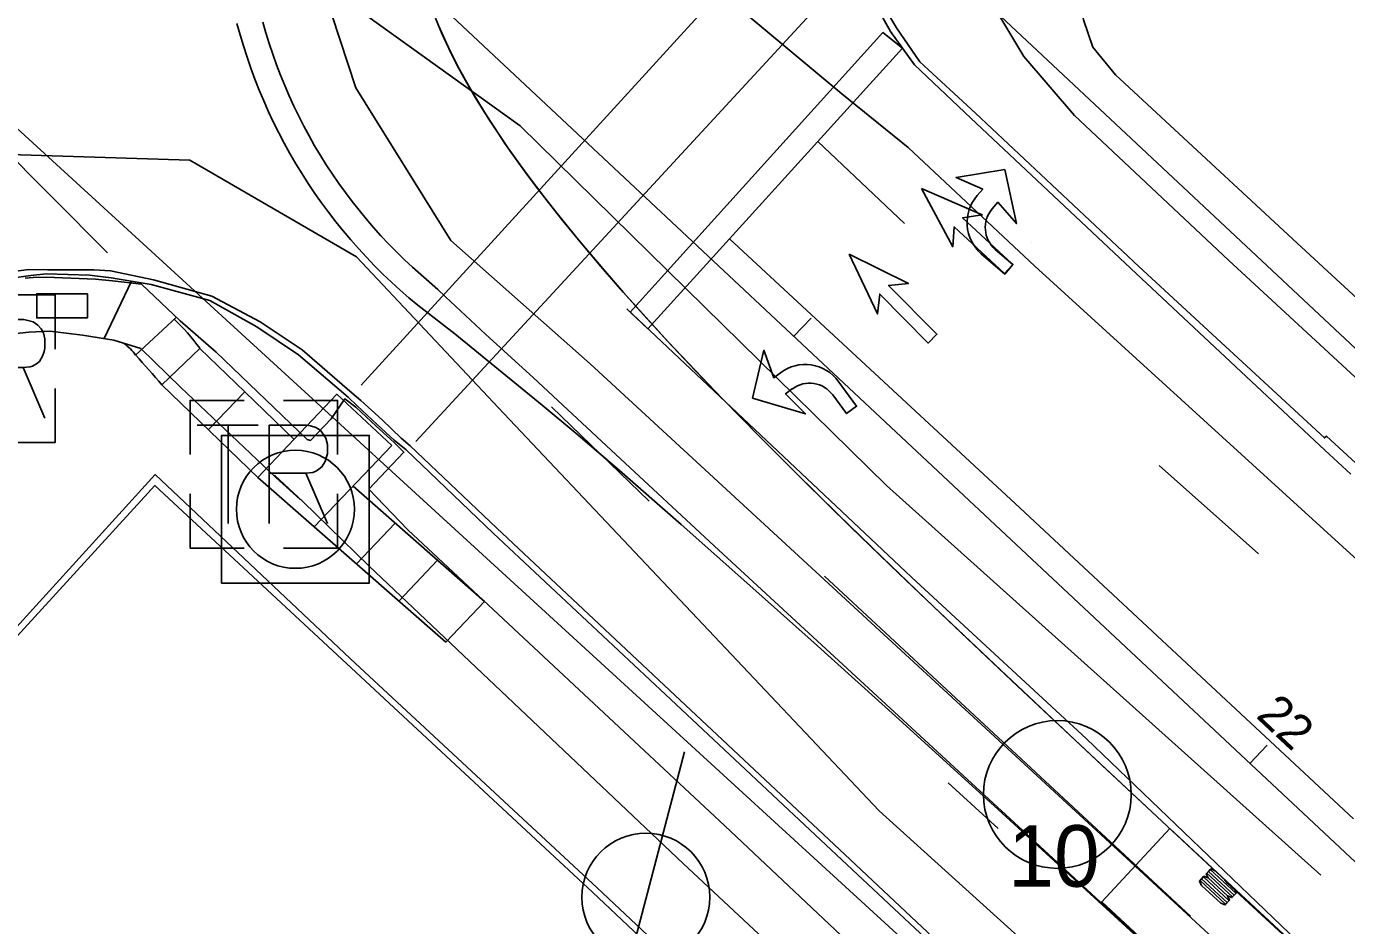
# Model space of a CAD drawing. Extents: x 1475900 to 1484331, y 375914 to 383395.
# Drawn here: x 1479629.9 to 1479735.5, y 379825.7 to 379897.7 of the extents above; entities that cross this region are included whole.
import ezdxf

# ---------------------------------------------------------------- set-up
doc = ezdxf.new("R2010")
doc.units = 0
for name, color, linetype in [('Default', 7, 'Continuous'), ('LT_X_Poles', 7, 'Continuous'), ('PM_X_Cells', 7, 'Continuous'), ('PM_X_Cells (Construction)', 7, 'Continuous'), ('PM_X_Channelizing_Line', 7, 'Continuous'), ('PM_X_CL_Double_Solid', 7, 'Continuous'), ('PM_X_Crosswalk', 7, 'Continuous'), ('PM_X_Lane_Line', 7, 'Continuous'), ('PM_X_Misc', 7, 'Continuous'), ('PM_X_Stop_Line', 7, 'Continuous'), ('PV_X_Curb', 7, 'Continuous'), ('PV_X_Walk', 7, 'Continuous'), ('RW_X_CL_20', 7, 'Continuous'), ('RW_X_Esmt_SH', 7, 'Continuous'), ('RW_X_Text', 7, 'Continuous'), ('SG_X_Poles', 7, 'Continuous'), ('SG_X_PullBox', 7, 'Continuous'), ('SG_X_PullBox (Construction)', 7, 'Continuous')]:
    doc.layers.add(name, color=color, linetype=linetype)

# ---------------------------------------------------------------- blocks, each defined once
blk = doc.blocks.new('SPOLE')
at = {"layer": 'SG_X_Poles'}
blk.add_lwpolyline([(-0.01905, -0.01905), (0.01905, -0.01905), (0.01905, 0.01905), (-0.01905, 0.01905)], close=True, dxfattribs=at)
blk.add_circle((0, 0), 0.01524, dxfattribs=at)
blk = doc.blocks.new('POINT_DISPLAY')
at = {"layer": 'Default'}
blk.add_line((0, 0), (0, 0), dxfattribs=at)
blk = doc.blocks.new('SIGPB')
at = {"layer": 'SG_X_PullBox'}
for p, q in [((-0.01722, 0.0127), (-0.00142, 0.0127)), ((-0.00922, 0.0127), (-0.00922, -0.0127)), ((0.01082, 0.0003), (0.01642, -0.0127))]:
    blk.add_line(p, q, dxfattribs=at)
for points in [[(-0.00508, 0.01905), (-0.01905, 0.01905), (-0.01905, 0.00508)], [(0.01905, 0.00508), (0.01905, 0.01905), (0.00508, 0.01905)], [(0.00142, -0.0127), (0.00142, 0.0127), (0.01102, 0.0127), (0.01202, 0.0125), (0.01342, 0.0121), (0.01402, 0.0117), (0.01462, 0.0113), (0.01542, 0.0103), (0.01602, 0.0093), (0.01642, 0.0077), (0.01642, 0.0053), (0.01622, 0.0045), (0.01582, 0.0033), (0.01502, 0.0019), (0.01422, 0.0013), (0.01362, 0.0009), (0.01322, 0.0007), (0.01262, 0.0005), (0.01082, 0.0003), (0.00142, 0.0003)], [(-0.01905, -0.00508), (-0.01905, -0.01905), (-0.00508, -0.01905)], [(0.00508, -0.01905), (0.01905, -0.01905), (0.01905, -0.00508)]]:
    blk.add_lwpolyline(points, dxfattribs=at)
at = {"layer": 'SG_X_PullBox (Construction)'}
blk.add_blockref('POINT_DISPLAY', (0, 0), dxfattribs=at)
blk = doc.blocks.new('LPOLE')
at = {"layer": 'LT_X_Poles'}
blk.add_lwpolyline([(0.00999, 0.03751), (-0.01001, -0.0385), (0.02, -0.0385)], dxfattribs=at)
blk.add_circle((0, 0), 0.01651, dxfattribs=at)
blk = doc.blocks.new('PMTHR')
at = {"layer": 'PM_X_Cells'}
blk.add_lwpolyline([(0, 0), (-1.27, -0.441), (-1.016, -0.127), (-2.413, -0.127), (-2.413, 0.127), (-1.016, 0.127), (-1.27, 0.441)], close=True, dxfattribs=at)
at = {"layer": 'PM_X_Cells (Construction)'}
for p in [(0, 0), (-2.413, 0)]:
    blk.add_blockref('POINT_DISPLAY', p, dxfattribs=at)
blk = doc.blocks.new('PMLFT')
at = {"layer": 'PM_X_Cells'}
for points in [[(-0.569, 0), (-0.569, 0), (-0.569, 0.169), (0, 0), (-0.65, 0.762), (-1.544, 0.085), (-0.975, 0.169), (-0.975, -0.009)], [(-1.559, -0.593), (-2.032, -0.593), (-2.032, -0.847), (-1.402, -0.847)]]:
    blk.add_lwpolyline(points, dxfattribs=at)
for centre, radius, end in [((-1.559, -0.009), 0.583, 0), ((-1.402, -0.013), 0.833, 0.9085)]:
    blk.add_arc(centre, radius, 270, end, dxfattribs=at)
at = {"layer": 'PM_X_Cells (Construction)'}
for p in [(-2.032, 0), (0, 0)]:
    blk.add_blockref('POINT_DISPLAY', p, dxfattribs=at)
blk = doc.blocks.new('PMRT')
at = {"layer": 'PM_X_Cells'}
for points in [[(-1.559, 0.593), (-2.032, 0.593), (-2.032, 0.847), (-1.402, 0.847)], [(-0.569, 0), (-0.569, 0), (-0.569, -0.169), (0, 0), (-0.65, -0.762), (-1.544, -0.085), (-0.975, -0.169), (-0.975, 0.009)]]:
    blk.add_lwpolyline(points, dxfattribs=at)
for centre, radius, start in [((-1.402, 0.013), 0.833, 359.0915), ((-1.559, 0.009), 0.583, 0)]:
    blk.add_arc(centre, radius, start, 90, dxfattribs=at)
at = {"layer": 'PM_X_Cells (Construction)'}
for p in [(-2.032, 0), (0, 0)]:
    blk.add_blockref('POINT_DISPLAY', p, dxfattribs=at)

msp = doc.modelspace()

# ---------------------------------------------------------------- linework, layer by layer
at = {"layer": 'PM_X_Channelizing_Line'}
msp.add_lwpolyline([(1479686.16, 379880.68), (1479709.4, 379859.14), (1479736.1, 379834.26)], dxfattribs=at)
at = {"layer": 'PM_X_CL_Double_Solid'}
msp.add_lwpolyline([(1479794.22, 379768.77), (1479779.09, 379781.77), (1479763.16, 379795.43), (1479746.62, 379810.62), (1479732.24, 379823.87), (1479714.72, 379840.65), (1479700.71, 379853.61), (1479677.93, 379875.07)], dxfattribs=at)
at = {"layer": 'PM_X_Crosswalk'}
for p, q in [((1479636.37, 379879.55), (1479574.01, 379942.24)), ((1479656.67, 379868.95), (1479694.22, 379910.08)), ((1479661.06, 379864.45), (1479696.23, 379902.55))]:
    msp.add_line(p, q, dxfattribs=at)
at = {"layer": 'PM_X_Lane_Line'}
for p, q in [((1479700.15, 379881.9), (1479693.22, 379888.46)), ((1479679.73, 379859.67), (1479671.91, 379867.24)), ((1479728.5, 379855.47), (1479720.54, 379862.54)), ((1479707.65, 379833.48), (1479703.66, 379837.14))]:
    msp.add_line(p, q, dxfattribs=at)
at = {"layer": 'PM_X_Misc'}
msp.add_line((1479693.75, 379853.68), (1479723.06, 379826.47), dxfattribs=at)
for points in [[(1479719.19, 379824.44), (1479707.65, 379835), (1479699.7, 379842.23), (1479692.92, 379848.35), (1479687.31, 379853.36), (1479682.27, 379857.82), (1479677.13, 379862.31), (1479673.86, 379865.13), (1479671.15, 379867.37), (1479664.18, 379873.07), (1479661.21, 379875.35), (1479660.49, 379875.95), (1479659.78, 379876.57), (1479659.09, 379877.21), (1479658.41, 379877.85), (1479657.74, 379878.52), (1479657.09, 379879.2), (1479656.46, 379879.89), (1479655.84, 379880.59), (1479655.23, 379881.31), (1479654.64, 379882.04), (1479654.07, 379882.79), (1479653.51, 379883.54), (1479652.97, 379884.31), (1479652.44, 379885.09), (1479651.94, 379885.88), (1479651.45, 379886.68), (1479650.97, 379887.5), (1479650.52, 379888.32), (1479650.08, 379889.15), (1479649.66, 379889.99), (1479649.26, 379890.84), (1479648.88, 379891.7), (1479648.51, 379892.57), (1479648.17, 379893.44), (1479647.84, 379894.32), (1479647.54, 379895.21), (1479647.25, 379896.1), (1479646.98, 379897), (1479646.73, 379897.91)], [(1479735, 379809.93), (1479685.31, 379855.76), (1479676.69, 379863.75), (1479670.46, 379869.55), (1479666.63, 379873.05), (1479663.42, 379876.03), (1479662.8, 379876.62), (1479660.79, 379878.39), (1479660.13, 379879), (1479659.49, 379879.63), (1479658.87, 379880.26), (1479658.25, 379880.92), (1479657.65, 379881.58), (1479657.07, 379882.26), (1479656.5, 379882.95), (1479655.95, 379883.66), (1479655.41, 379884.37), (1479654.88, 379885.1), (1479654.38, 379885.84), (1479653.88, 379886.59), (1479653.41, 379887.35), (1479652.95, 379888.12), (1479652.51, 379888.9), (1479652.08, 379889.68), (1479651.67, 379890.48), (1479651.28, 379891.29), (1479650.91, 379892.1), (1479650.55, 379892.93), (1479650.22, 379893.76), (1479649.9, 379894.59), (1479649.6, 379895.44), (1479649.31, 379896.29), (1479649.05, 379897.14), (1479648.8, 379898)], [(1479662.61, 379898.32), (1479663.13, 379897.09), (1479663.71, 379895.84), (1479664.34, 379894.59), (1479665.02, 379893.34), (1479665.75, 379892.08), (1479666.52, 379890.83), (1479667.33, 379889.57), (1479668.17, 379888.31), (1479669.05, 379887.06), (1479669.96, 379885.81), (1479671.37, 379883.95), (1479672.82, 379882.1), (1479674.32, 379880.27), (1479675.86, 379878.45), (1479677.43, 379876.64), (1479679.03, 379874.85), (1479681.2, 379872.48), (1479683.41, 379870.14), (1479685.66, 379867.8), (1479688.49, 379864.91), (1479691.37, 379862.03), (1479694.85, 379858.61), (1479698.36, 379855.2), (1479702.49, 379851.24), (1479707.83, 379846.17), (1479713.8, 379840.57), (1479721.58, 379833.3), (1479725.78, 379829.4), (1479725.98, 379829.12), (1479740.44, 379815.79)], [(1479662.85, 379897.74), (1479663.49, 379896.33), (1479663.82, 379895.64), (1479664.51, 379894.28), (1479665.25, 379892.95), (1479665.63, 379892.29), (1479666.84, 379890.32), (1479667.69, 379889.04), (1479668.55, 379887.77), (1479669.91, 379885.88), (1479670.82, 379884.66), (1479672.24, 379882.83), (1479674.17, 379880.45), (1479676.17, 379878.1), (1479677.67, 379876.38), (1479679.72, 379874.1), (1479681.28, 379872.4), (1479682.87, 379870.71), (1479685.53, 379867.93), (1479688.76, 379864.64), (1479692.01, 379861.39), (1479695.87, 379857.61), (1479699.71, 379853.9), (1479704.18, 379849.63), (1479709.2, 379844.88), (1479715.95, 379838.55), (1479724.38, 379830.7), (1479743.38, 379813.07)], [(1479726.67, 379828.3), (1479724.62, 379830.2), (1479724.49, 379830.06), (1479726.54, 379828.15), (1479726.4, 379828.01), (1479724.35, 379829.91), (1479724.3, 379829.86), (1479724.47, 379829.53), (1479726.01, 379828.1), (1479726.36, 379827.96), (1479726.72, 379828.35), (1479726.55, 379828.68), (1479725.01, 379830.11), (1479724.67, 379830.25), (1479724.3, 379829.86)], [(1479726.13, 379827.71), (1479724.08, 379829.62), (1479723.94, 379829.47), (1479725.99, 379827.57), (1479725.86, 379827.42), (1479723.81, 379829.33), (1479723.76, 379829.28), (1479723.93, 379828.94), (1479725.47, 379827.51), (1479725.81, 379827.37), (1479726.18, 379827.76), (1479726.01, 379828.1), (1479724.47, 379829.53), (1479724.12, 379829.67), (1479723.76, 379829.28)]]:
    msp.add_lwpolyline(points, dxfattribs=at)
msp.add_lwpolyline([(1479737.93, 379807.21), (1479715.94, 379827.62), (1479718.67, 379830.55), (1479721.39, 379833.48), (1479743.38, 379813.07), (1479740.65, 379810.14)], close=True, dxfattribs=at)
msp.add_circle((1479712.39, 379836.21), 5.91, dxfattribs=at)
at = {"layer": 'PM_X_Stop_Line'}
msp.add_lwpolyline([(1479700, 379895.92), (1479698.43, 379897.17), (1479678.21, 379874.81), (1479679.62, 379873.47)], close=True, dxfattribs=at)
at = {"layer": 'PV_X_Curb'}
msp.add_line((1479636.09, 379872.69), (1479638.29, 379877.28), dxfattribs=at)
for points in [[(1479735.87, 379861.85), (1479733.79, 379863.76), (1479718.7, 379877.9), (1479705.48, 379890.33), (1479700.95, 379894.58), (1479699.05, 379897.26), (1479697.78, 379899.5), (1479696.44, 379902.73), (1479695.78, 379905.4), (1479695.47, 379907.42), (1479695.14, 379911.53), (1479695.08, 379915.32), (1479695.47, 379917.32), (1479696.05, 379920.61), (1479697.32, 379923.3), (1479700.06, 379927.56), (1479702.83, 379930.77), (1479705.86, 379933.57), (1479707.03, 379934.35), (1479708.06, 379934.88), (1479711.18, 379937.55)], [(1479714.57, 379931.72), (1479714.77, 379922.6), (1479714.23, 379900.01), (1479714.49, 379898.19), (1479715.22, 379896), (1479717.04, 379893.8), (1479731.94, 379880.01), (1479745.71, 379867.31), (1479763.19, 379850.75), (1479775.06, 379839.58), (1479781.93, 379833.12), (1479783.78, 379830.71), (1479784.21, 379828.71), (1479783.14, 379825.91)], [(1479738.29, 379860.89), (1479733.93, 379864.88), (1479733.77, 379864.74), (1479718.9, 379878.45), (1479705.83, 379890.72), (1479701.38, 379894.84), (1479699.53, 379897.55), (1479698.18, 379899.76)], [(1479624.52, 379877.49), (1479630.08, 379878.22), (1479631.57, 379878.19), (1479635.27, 379878.18), (1479636.61, 379878.11), (1479640.05, 379877.39), (1479644.71, 379876.09), (1479648.6, 379874.02), (1479651.95, 379871.78), (1479655.96, 379868.33), (1479656.65, 379867.73), (1479658.34, 379866.2), (1479659.87, 379864.73), (1479660.6, 379864.1), (1479667.53, 379857.52), (1479681.36, 379844.56), (1479695.38, 379831.42), (1479709.51, 379818.13)], [(1479624.77, 379877), (1479630.24, 379877.74), (1479631.47, 379877.86), (1479634.93, 379877.76), (1479636.66, 379877.55), (1479639.86, 379877.01), (1479644.56, 379875.73), (1479648.33, 379873.64), (1479651.66, 379871.4), (1479655.64, 379868), (1479656.34, 379867.3), (1479657.96, 379865.82), (1479659.31, 379864.57), (1479660.28, 379863.79), (1479667.24, 379857.12), (1479681.02, 379844.21), (1479695.13, 379830.98), (1479709.33, 379817.71)], [(1479752.34, 379756.82), (1479734.89, 379773.49), (1479717.23, 379789.66), (1479699.3, 379806.4), (1479688.16, 379794.93), (1479685.53, 379793.9), (1479682.73, 379795.16), (1479681.26, 379797.55), (1479682.49, 379800.75), (1479693.46, 379811.91), (1479675.55, 379828.75), (1479655.83, 379847.06), (1479640.19, 379861.81), (1479628.56, 379849)], [(1479751.93, 379756.63), (1479734.45, 379772.98), (1479716.7, 379789.46), (1479699.4, 379805.74), (1479688.56, 379794.79), (1479685.72, 379793.29), (1479682.29, 379794.8), (1479680.73, 379797.25), (1479682.17, 379801.19), (1479692.65, 379811.91), (1479675.18, 379828.39), (1479655.51, 379846.68), (1479640.15, 379860.93), (1479629.13, 379848.87)]]:
    msp.add_lwpolyline(points, dxfattribs=at)
for points in [[(1479634.76, 379876.27), (1479634.76, 379874.34), (1479630.71, 379874.34), (1479630.71, 379876.27)], [(1479659.12, 379864.14), (1479652.91, 379857.63), (1479648.4, 379861.58), (1479654.73, 379868.23)]]:
    msp.add_lwpolyline(points, close=True, dxfattribs=at)
at = {"layer": 'PV_X_Walk'}
for p, q in [((1479641.88, 379874.41), (1479638.62, 379871.36)), ((1479643.77, 379871.9), (1479640.72, 379868.99)), ((1479643.77, 379871.9), (1479647.37, 379868.43)), ((1479640.72, 379868.99), (1479648.4, 379861.58)), ((1479647.37, 379868.43), (1479644.44, 379865.4)), ((1479647.37, 379868.43), (1479651.32, 379864.61)), ((1479656.02, 379860.89), (1479666.55, 379851.65)), ((1479652.91, 379857.63), (1479663.45, 379848.39)), ((1479659.4, 379857.92), (1479656.3, 379854.66)), ((1479662.79, 379854.95), (1479659.68, 379851.69)), ((1479666.55, 379851.65), (1479663.45, 379848.39))]:
    msp.add_line(p, q, dxfattribs=at)
for points in [[(1479714.41, 379931.65), (1479709.59, 379929.39), (1479706.36, 379927.01), (1479703.83, 379924.36), (1479702.38, 379922.18), (1479701.6, 379920.68), (1479701.23, 379918.28), (1479701.22, 379916.7), (1479701.87, 379912.68), (1479703.86, 379906.89), (1479705.42, 379903.15), (1479707.31, 379899.27), (1479709.71, 379895.26), (1479713.76, 379890.53), (1479726.08, 379878.96), (1479737.97, 379867.99), (1479746.24, 379860.49), (1479749.39, 379863.57), (1479751.94, 379861.3), (1479749.04, 379858.04), (1479762.48, 379845.22), (1479775.26, 379833.23), (1479781.25, 379827.72), (1479783.04, 379825.88)], [(1479705.73, 379814.89), (1479685.77, 379833.71), (1479660.41, 379857.39), (1479657.29, 379860.63), (1479660.09, 379863.59), (1479659.32, 379864.38), (1479657.86, 379865.69), (1479656.25, 379867.19), (1479655.37, 379867.88), (1479654.27, 379866.26), (1479652.63, 379864.54), (1479652.35, 379864.61), (1479645.06, 379871.59), (1479642.19, 379874.12), (1479639.08, 379877.04), (1479636.77, 379877.32), (1479635.41, 379877.45), (1479631.46, 379877.61), (1479630.42, 379877.57), (1479629.78, 379877.53)], [(1479767.05, 379754.29), (1479759.06, 379761.03), (1479757.31, 379762.48), (1479754.26, 379765.1), (1479744.26, 379773.56), (1479732.86, 379783.69), (1479719.35, 379796.38), (1479703.03, 379811.46), (1479682.44, 379830.69), (1479657.3, 379854.47), (1479652, 379859.64), (1479649.77, 379861.74), (1479651.8, 379859.82), (1479649.83, 379861.57), (1479642.24, 379868.78), (1479639.04, 379871.89), (1479636.88, 379872.56), (1479634.38, 379872.97), (1479631.75, 379873.28), (1479630.08, 379873.21), (1479625.85, 379872.76)]]:
    msp.add_lwpolyline(points, dxfattribs=at)
for centre, radius, start, end in [((1479628.39, 379860.4), 19.21, 36.808, 46.2666), ((1479635.39, 379869.13), 3.92, 34.5576, 53.9557), ((1479511.61, 379756.72), 171.1, 41.007, 42.0676)]:
    msp.add_arc(centre, radius, start, end, dxfattribs=at)
at = {"layer": 'RW_X_CL_20'}
for p, q in [((1479691.31, 379872.87), (1479692.68, 379874.33)), ((1479727.81, 379838.69), (1479729.18, 379840.15))]:
    msp.add_line(p, q, dxfattribs=at)
msp.add_lwpolyline([(1477185.15, 382318.79), (1478151.68, 381373.49), (1479566.7, 379989.54), (1480555.97, 379063.33), (1481343.87, 378335.5), (1481853.32, 377853.22), (1482587.9, 377143.51), (1482849.67, 376882.07), (1483668.91, 376080.34), (1483878.1, 376026.7), (1484025.82, 375988.83), (1484313.71, 375915.02)], dxfattribs=at)
at = {"layer": 'RW_X_Esmt_SH'}
msp.add_line((1479687.35, 379917.68), (1479967.32, 379655.56), dxfattribs=at)
msp.add_lwpolyline([(1479610.78, 379906.29), (1479798.35, 379734.62), (1479796.8, 379733.01), (1479926.31, 379611.76)], dxfattribs=at)
at = {"layer": 'RW_X_Text'}
for points in [[(1479792.31, 379997.56), (1479688.12, 379945.87), (1479680.71, 379942), (1479661.48, 379931.68), (1479658.87, 379928.92), (1479653.52, 379923.03), (1479651.72, 379914.38), (1479652.44, 379904.37), (1479656.24, 379892.75), (1479663.84, 379880.53), (1479675, 379870.68), (1479716.91, 379832.05), (1479737.94, 379812.66)], [(1479797.55, 379798.42), (1479779.29, 379815.04), (1479755.95, 379837.17), (1479710.6, 379878.47), (1479700.46, 379887.97), (1479695.14, 379892.26), (1479687.63, 379898.54), (1479684.65, 379909.71), (1479684.09, 379918.26), (1479685.98, 379925.49), (1479693.36, 379933.84), (1479703.54, 379940.07), (1479719.59, 379947.28), (1479755.69, 379965.71), (1479770.46, 379973.23)], [(1479733.47, 379829.75), (1479698.71, 379860.92), (1479681.21, 379878.12), (1479669.41, 379889.71), (1479654.95, 379900.1), (1479640.42, 379905.58), (1479623.99, 379909.38), (1479606.71, 379909.37), (1479595.29, 379905.22), (1479570.47, 379896.19), (1479545.09, 379885.58), (1479522.33, 379874.3), (1479499.6, 379861.91)], [(1479448.85, 379819.27), (1479488.56, 379843.18), (1479509.21, 379852.71), (1479530.16, 379858.34), (1479557.4, 379865.65), (1479587.55, 379875.68), (1479607.72, 379882.39), (1479617.76, 379885.73), (1479628.56, 379887.41), (1479642.96, 379886.97), (1479656.29, 379879.24), (1479668.08, 379866.7), (1479698.14, 379834.91), (1479745.89, 379791.74)]]:
    msp.add_lwpolyline(points, dxfattribs=at)

# ---------------------------------------------------------------- block references
at = {"layer": 'LT_X_Poles', "xscale": 310.00000000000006, "yscale": 310.00000000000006}
msp.add_blockref('LPOLE', (1479679.46, 379827.99), dxfattribs=at)
at = {"layer": 'PM_X_Cells'}
for name, p, xscale, yscale, rotation in [('PMRT', (1479704.28, 379885.59), 3.937007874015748, 3.937007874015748, 139.4217946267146), ('PMTHR', (1479701.53, 379884.71), 3.937007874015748, 3.9370078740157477, 137.1982365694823), ('PMTHR', (1479695.72, 379879.44), 3.9370078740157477, 3.9370078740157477, 134.67710368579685), ('PMLFT', (1479688.91, 379871.76), 3.937007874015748, 3.937007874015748, 126.17693352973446)]:
    msp.add_blockref(name, p, dxfattribs=dict(at, xscale=xscale, yscale=yscale, rotation=rotation))
at = {"layer": 'SG_X_Poles', "xscale": 310.00000000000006, "yscale": 310.00000000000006}
msp.add_blockref('SPOLE', (1479651.41, 379859.03), dxfattribs=at)
at = {"layer": 'SG_X_PullBox', "xscale": 310.00000000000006, "yscale": 310.00000000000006}
for p in [(1479626.27, 379870.27), (1479648.88, 379861.83)]:
    msp.add_blockref('SIGPB', p, dxfattribs=at)

# ---------------------------------------------------------------- texts
at = {"layer": 'PM_X_Misc'}
msp.add_text('10', height=4.921, dxfattribs=at).set_placement((1479708.46, 379828.83))
at = {"layer": 'RW_X_CL_20'}
msp.add_text('22', height=2.8, rotation=316.8859, dxfattribs=at).set_placement((1479728.21, 379842.43))

doc.saveas('drawing.dxf')
